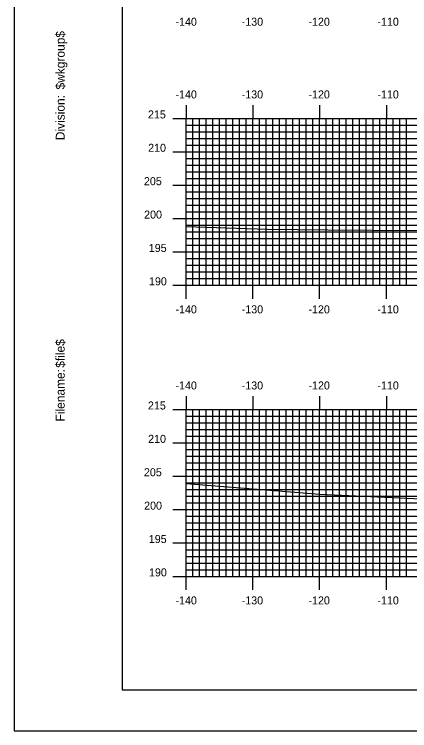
# Model space of a CAD drawing. Extents: x 852087 to 852430, y 366898 to 367118.
# Drawn here: x 852086.7 to 852146, y 366898.4 to 367005.7 of the extents above; entities that cross this region are included whole.
import ezdxf

# ---------------------------------------------------------------- set-up
doc = ezdxf.new("R2010")
doc.units = 0
for name, color, linetype in [('BORDER', 7, 'Continuous'), ('H_V ANNOTATION', 7, 'Continuous'), ('MAJOR', 7, 'Continuous'), ('MINOR', 7, 'Continuous'), ('PLOT BOUNDARY', 7, 'Continuous'), ('S_Roadway_Centerline', 7, 'Continuous')]:
    doc.layers.add(name, color=color, linetype=linetype)

msp = doc.modelspace()

# ---------------------------------------------------------------- linework, layer by layer
at = {"layer": 'BORDER'}
msp.add_lwpolyline([(852102.93, 366904.47), (852422.93, 366904.47), (852422.93, 367114.47), (852102.93, 367114.47)], close=True, dxfattribs=at)
at = {"layer": 'MAJOR'}
for p, q in [((852112.53, 366992.07), (852112.53, 366990.07)), ((852122.53, 366992.07), (852122.53, 366990.07)), ((852132.53, 366992.07), (852132.53, 366990.07)), ((852142.53, 366992.07), (852142.53, 366990.07)), ((852110.53, 366990.07), (852112.53, 366990.07)), ((852112.53, 366990.07), (852392.53, 366990.07)), ((852112.53, 366965.07), (852112.53, 366990.07)), ((852112.53, 366965.07), (852112.53, 366990.07)), ((852112.53, 366990.07), (852392.53, 366990.07)), ((852122.53, 366965.07), (852122.53, 366990.07)), ((852132.53, 366965.07), (852132.53, 366990.07)), ((852142.53, 366965.07), (852142.53, 366990.07)), ((852110.53, 366985.07), (852112.53, 366985.07)), ((852112.53, 366985.07), (852392.53, 366985.07)), ((852110.53, 366980.07), (852112.53, 366980.07)), ((852112.53, 366980.07), (852392.53, 366980.07)), ((852110.53, 366975.07), (852112.53, 366975.07)), ((852112.53, 366975.07), (852392.53, 366975.07)), ((852110.53, 366970.07), (852112.53, 366970.07)), ((852112.53, 366970.07), (852392.53, 366970.07)), ((852110.53, 366965.07), (852112.53, 366965.07)), ((852112.53, 366965.07), (852392.53, 366965.07)), ((852112.53, 366965.07), (852392.53, 366965.07)), ((852112.53, 366963.06), (852112.53, 366965.07)), ((852122.53, 366963.06), (852122.53, 366965.07)), ((852132.53, 366963.06), (852132.53, 366965.07)), ((852142.53, 366963.06), (852142.53, 366965.07)), ((852112.53, 366948.48), (852112.53, 366946.47)), ((852122.53, 366948.48), (852122.53, 366946.47)), ((852132.53, 366948.48), (852132.53, 366946.47)), ((852142.53, 366948.48), (852142.53, 366946.47)), ((852110.53, 366946.47), (852112.53, 366946.47)), ((852112.53, 366946.47), (852392.53, 366946.47)), ((852112.53, 366921.47), (852112.53, 366946.47)), ((852112.53, 366921.47), (852112.53, 366946.47)), ((852112.53, 366946.47), (852392.53, 366946.47)), ((852122.53, 366921.47), (852122.53, 366946.47)), ((852132.53, 366921.47), (852132.53, 366946.47)), ((852142.53, 366921.47), (852142.53, 366946.47)), ((852110.53, 366941.47), (852112.53, 366941.47)), ((852112.53, 366941.47), (852392.53, 366941.47)), ((852110.53, 366936.47), (852112.53, 366936.47)), ((852112.53, 366936.47), (852392.53, 366936.47)), ((852110.53, 366931.47), (852112.53, 366931.47)), ((852112.53, 366931.47), (852392.53, 366931.47)), ((852110.53, 366926.47), (852112.53, 366926.47)), ((852112.53, 366926.47), (852392.53, 366926.47)), ((852110.53, 366921.47), (852112.53, 366921.47)), ((852112.53, 366921.47), (852392.53, 366921.47)), ((852112.53, 366921.47), (852392.53, 366921.47)), ((852112.53, 366919.47), (852112.53, 366921.47)), ((852122.53, 366919.47), (852122.53, 366921.47)), ((852132.53, 366919.47), (852132.53, 366921.47)), ((852142.53, 366919.47), (852142.53, 366921.47))]:
    msp.add_line(p, q, dxfattribs=at)
at = {"layer": 'MINOR'}
for p, q in [((852113.53, 366965.07), (852113.53, 366990.07)), ((852114.53, 366965.07), (852114.53, 366990.07)), ((852115.53, 366965.07), (852115.53, 366990.07)), ((852116.53, 366965.07), (852116.53, 366990.07)), ((852117.53, 366965.07), (852117.53, 366990.07)), ((852118.53, 366965.07), (852118.53, 366990.07)), ((852119.53, 366965.07), (852119.53, 366990.07)), ((852120.53, 366965.07), (852120.53, 366990.07)), ((852121.53, 366965.07), (852121.53, 366990.07)), ((852123.53, 366965.07), (852123.53, 366990.07)), ((852124.53, 366965.07), (852124.53, 366990.07)), ((852125.53, 366965.07), (852125.53, 366990.07)), ((852126.53, 366965.07), (852126.53, 366990.07)), ((852127.53, 366965.07), (852127.53, 366990.07)), ((852128.53, 366965.07), (852128.53, 366990.07)), ((852129.53, 366965.07), (852129.53, 366990.07)), ((852130.53, 366965.07), (852130.53, 366990.07)), ((852131.53, 366965.07), (852131.53, 366990.07)), ((852133.53, 366965.07), (852133.53, 366990.07)), ((852134.53, 366965.07), (852134.53, 366990.07)), ((852135.53, 366965.07), (852135.53, 366990.07)), ((852136.53, 366965.07), (852136.53, 366990.07)), ((852137.53, 366965.07), (852137.53, 366990.07)), ((852138.53, 366965.07), (852138.53, 366990.07)), ((852139.53, 366965.07), (852139.53, 366990.07)), ((852140.53, 366965.07), (852140.53, 366990.07)), ((852141.53, 366965.07), (852141.53, 366990.07)), ((852143.53, 366965.07), (852143.53, 366990.07)), ((852144.53, 366965.07), (852144.53, 366990.07)), ((852145.53, 366965.07), (852145.53, 366990.07)), ((852112.53, 366989.07), (852392.53, 366989.07)), ((852112.53, 366989.07), (852114.54, 366989.07)), ((852112.53, 366988.07), (852392.53, 366988.07)), ((852112.53, 366988.07), (852114.54, 366988.07)), ((852112.53, 366987.07), (852392.53, 366987.07)), ((852112.53, 366987.07), (852114.54, 366987.07)), ((852112.53, 366986.07), (852392.53, 366986.07)), ((852112.53, 366986.07), (852114.54, 366986.07)), ((852112.53, 366984.07), (852392.53, 366984.07)), ((852112.53, 366984.07), (852114.54, 366984.07)), ((852112.53, 366983.07), (852392.53, 366983.07)), ((852112.53, 366983.07), (852114.54, 366983.07)), ((852112.53, 366982.07), (852392.53, 366982.07)), ((852112.53, 366982.07), (852114.54, 366982.07)), ((852112.53, 366981.07), (852392.53, 366981.07)), ((852112.53, 366981.07), (852114.54, 366981.07)), ((852112.53, 366979.07), (852392.53, 366979.07)), ((852112.53, 366979.07), (852114.54, 366979.07)), ((852112.53, 366978.07), (852392.53, 366978.07)), ((852112.53, 366978.07), (852114.54, 366978.07)), ((852112.53, 366977.07), (852392.53, 366977.07)), ((852112.53, 366977.07), (852114.54, 366977.07)), ((852112.53, 366976.07), (852392.53, 366976.07)), ((852112.53, 366976.07), (852114.54, 366976.07)), ((852112.53, 366974.07), (852392.53, 366974.07)), ((852112.53, 366974.07), (852114.54, 366974.07)), ((852112.53, 366973.07), (852392.53, 366973.07)), ((852112.53, 366973.07), (852114.54, 366973.07)), ((852112.53, 366972.07), (852392.53, 366972.07)), ((852112.53, 366972.07), (852114.54, 366972.07)), ((852112.53, 366971.07), (852392.53, 366971.07)), ((852112.53, 366971.07), (852114.54, 366971.07)), ((852112.53, 366969.07), (852392.53, 366969.07)), ((852112.53, 366969.07), (852114.54, 366969.07)), ((852112.53, 366968.07), (852392.53, 366968.07)), ((852112.53, 366968.07), (852114.54, 366968.07)), ((852112.53, 366967.07), (852392.53, 366967.07)), ((852112.53, 366967.07), (852114.54, 366967.07)), ((852112.53, 366966.07), (852392.53, 366966.07)), ((852112.53, 366966.07), (852114.54, 366966.07)), ((852113.53, 366921.47), (852113.53, 366946.47)), ((852114.53, 366921.47), (852114.53, 366946.47)), ((852115.53, 366921.47), (852115.53, 366946.47)), ((852116.53, 366921.47), (852116.53, 366946.47)), ((852117.53, 366921.47), (852117.53, 366946.47)), ((852118.53, 366921.47), (852118.53, 366946.47)), ((852119.53, 366921.47), (852119.53, 366946.47)), ((852120.53, 366921.47), (852120.53, 366946.47)), ((852121.53, 366921.47), (852121.53, 366946.47)), ((852123.53, 366921.47), (852123.53, 366946.47)), ((852124.53, 366921.47), (852124.53, 366946.47)), ((852125.53, 366921.47), (852125.53, 366946.47)), ((852126.53, 366921.47), (852126.53, 366946.47)), ((852127.53, 366921.47), (852127.53, 366946.47)), ((852128.53, 366921.47), (852128.53, 366946.47)), ((852129.53, 366921.47), (852129.53, 366946.47)), ((852130.53, 366921.47), (852130.53, 366946.47)), ((852131.53, 366921.47), (852131.53, 366946.47)), ((852133.53, 366921.47), (852133.53, 366946.47)), ((852134.53, 366921.47), (852134.53, 366946.47)), ((852135.53, 366921.47), (852135.53, 366946.47)), ((852136.53, 366921.47), (852136.53, 366946.47)), ((852137.53, 366921.47), (852137.53, 366946.47)), ((852138.53, 366921.47), (852138.53, 366946.47)), ((852139.53, 366921.47), (852139.53, 366946.47)), ((852140.53, 366921.47), (852140.53, 366946.47)), ((852141.53, 366921.47), (852141.53, 366946.47)), ((852143.53, 366921.47), (852143.53, 366946.47)), ((852144.53, 366921.47), (852144.53, 366946.47)), ((852145.53, 366921.47), (852145.53, 366946.47)), ((852112.53, 366945.47), (852392.53, 366945.47)), ((852112.53, 366945.47), (852114.54, 366945.47)), ((852112.53, 366944.47), (852392.53, 366944.47)), ((852112.53, 366944.47), (852114.54, 366944.47)), ((852112.53, 366943.47), (852392.53, 366943.47)), ((852112.53, 366943.47), (852114.54, 366943.47)), ((852112.53, 366942.47), (852392.53, 366942.47)), ((852112.53, 366942.47), (852114.54, 366942.47)), ((852112.53, 366940.47), (852392.53, 366940.47)), ((852112.53, 366940.47), (852114.54, 366940.47)), ((852112.53, 366939.47), (852392.53, 366939.47)), ((852112.53, 366939.47), (852114.54, 366939.47)), ((852112.53, 366938.47), (852392.53, 366938.47)), ((852112.53, 366938.47), (852114.54, 366938.47)), ((852112.53, 366937.47), (852392.53, 366937.47)), ((852112.53, 366937.47), (852114.54, 366937.47)), ((852112.53, 366935.47), (852392.53, 366935.47)), ((852112.53, 366935.47), (852114.54, 366935.47)), ((852112.53, 366934.47), (852392.53, 366934.47)), ((852112.53, 366934.47), (852114.54, 366934.47)), ((852112.53, 366933.47), (852392.53, 366933.47)), ((852112.53, 366933.47), (852114.54, 366933.47)), ((852112.53, 366932.47), (852392.53, 366932.47)), ((852112.53, 366932.47), (852114.54, 366932.47)), ((852112.53, 366930.47), (852392.53, 366930.47)), ((852112.53, 366930.47), (852114.54, 366930.47)), ((852112.53, 366929.47), (852392.53, 366929.47)), ((852112.53, 366929.47), (852114.54, 366929.47)), ((852112.53, 366928.47), (852392.53, 366928.47)), ((852112.53, 366928.47), (852114.54, 366928.47)), ((852112.53, 366927.47), (852392.53, 366927.47)), ((852112.53, 366927.47), (852114.54, 366927.47)), ((852112.53, 366925.47), (852392.53, 366925.47)), ((852112.53, 366925.47), (852114.54, 366925.47)), ((852112.53, 366924.47), (852392.53, 366924.47)), ((852112.53, 366924.47), (852114.54, 366924.47)), ((852112.53, 366923.47), (852392.53, 366923.47)), ((852112.53, 366923.47), (852114.54, 366923.47)), ((852112.53, 366922.47), (852392.53, 366922.47)), ((852112.53, 366922.47), (852114.54, 366922.47))]:
    msp.add_line(p, q, dxfattribs=at)
at = {"layer": 'PLOT BOUNDARY'}
msp.add_lwpolyline([(852086.74, 366898.35), (852426.74, 366898.35), (852426.74, 367118.35), (852086.74, 367118.35)], close=True, dxfattribs=at)
at = {"layer": 'S_Roadway_Centerline'}
for points in [[(852112.53, 366973.86), (852124.68, 366973.49), (852133.77, 366973.36), (852140.47, 366973.35), (852149.48, 366973.27), (852162.38, 366973.27), (852171.72, 366973.53), (852178.06, 366973.52), (852179.53, 366973.46), (852186.98, 366974.2), (852188.59, 366974.38), (852188.84, 366974.38), (852191.07, 366974.67), (852199.75, 366975.7), (852204.72, 366976.2), (852217.91, 366978.1)], [(852112.53, 366935.36), (852132.58, 366933.8), (852148.82, 366933.04), (852157.64, 366932.81), (852172.52, 366933.01), (852184.46, 366933.06), (852196.36, 366931.98), (852205.06, 366931.28), (852209.27, 366931.23)]]:
    msp.add_lwpolyline(points, dxfattribs=at)

# ---------------------------------------------------------------- texts
at = {"layer": 'BORDER'}
for s, p in [('$wkgroup$', (852094.3, 366994.41)), ('Division:', (852094.3, 366986.81)), ('$file$', (852094.3, 366952.72)), ('Filename:', (852094.3, 366944.67))]:
    msp.add_text(s, height=1.339, rotation=90, dxfattribs=at).set_placement(p)
at = {"layer": 'H_V ANNOTATION'}
for s, p in [('-140', (852110.91, 367003.96)), ('-130', (852120.84, 367003.96)), ('-120', (852130.85, 367003.96)), ('-110', (852141.19, 367003.96)), ('-140', (852110.91, 366993.07)), ('-130', (852120.84, 366993.07)), ('-120', (852130.85, 366993.07)), ('-110', (852141.19, 366993.07)), ('215', (852106.78, 366990.07)), ('210', (852106.81, 366985.07)), ('205', (852106.18, 366980.07)), ('200', (852106.21, 366975.07)), ('195', (852106.91, 366970.07)), ('190', (852106.94, 366965.07)), ('-140', (852110.91, 366960.87)), ('-130', (852120.84, 366960.87)), ('-120', (852130.85, 366960.87)), ('-110', (852141.19, 366960.87)), ('-140', (852110.91, 366949.47)), ('-130', (852120.84, 366949.47)), ('-120', (852130.85, 366949.47)), ('-110', (852141.19, 366949.47)), ('215', (852106.78, 366946.47)), ('210', (852106.81, 366941.47)), ('205', (852106.18, 366936.47)), ('200', (852106.21, 366931.47)), ('195', (852106.91, 366926.47)), ('190', (852106.94, 366921.47)), ('-140', (852110.91, 366917.27)), ('-130', (852120.84, 366917.27)), ('-120', (852130.85, 366917.27)), ('-110', (852141.19, 366917.27))]:
    msp.add_text(s, height=1.2, dxfattribs=at).set_placement(p)
at = {"layer": 'MAJOR'}
for p in [(852112.52, 366965.07), (852112.52, 366921.47)]:
    msp.add_text('-', height=0.012, dxfattribs=at).set_placement(p)

doc.saveas('drawing.dxf')
